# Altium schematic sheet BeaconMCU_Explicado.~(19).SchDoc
size A4
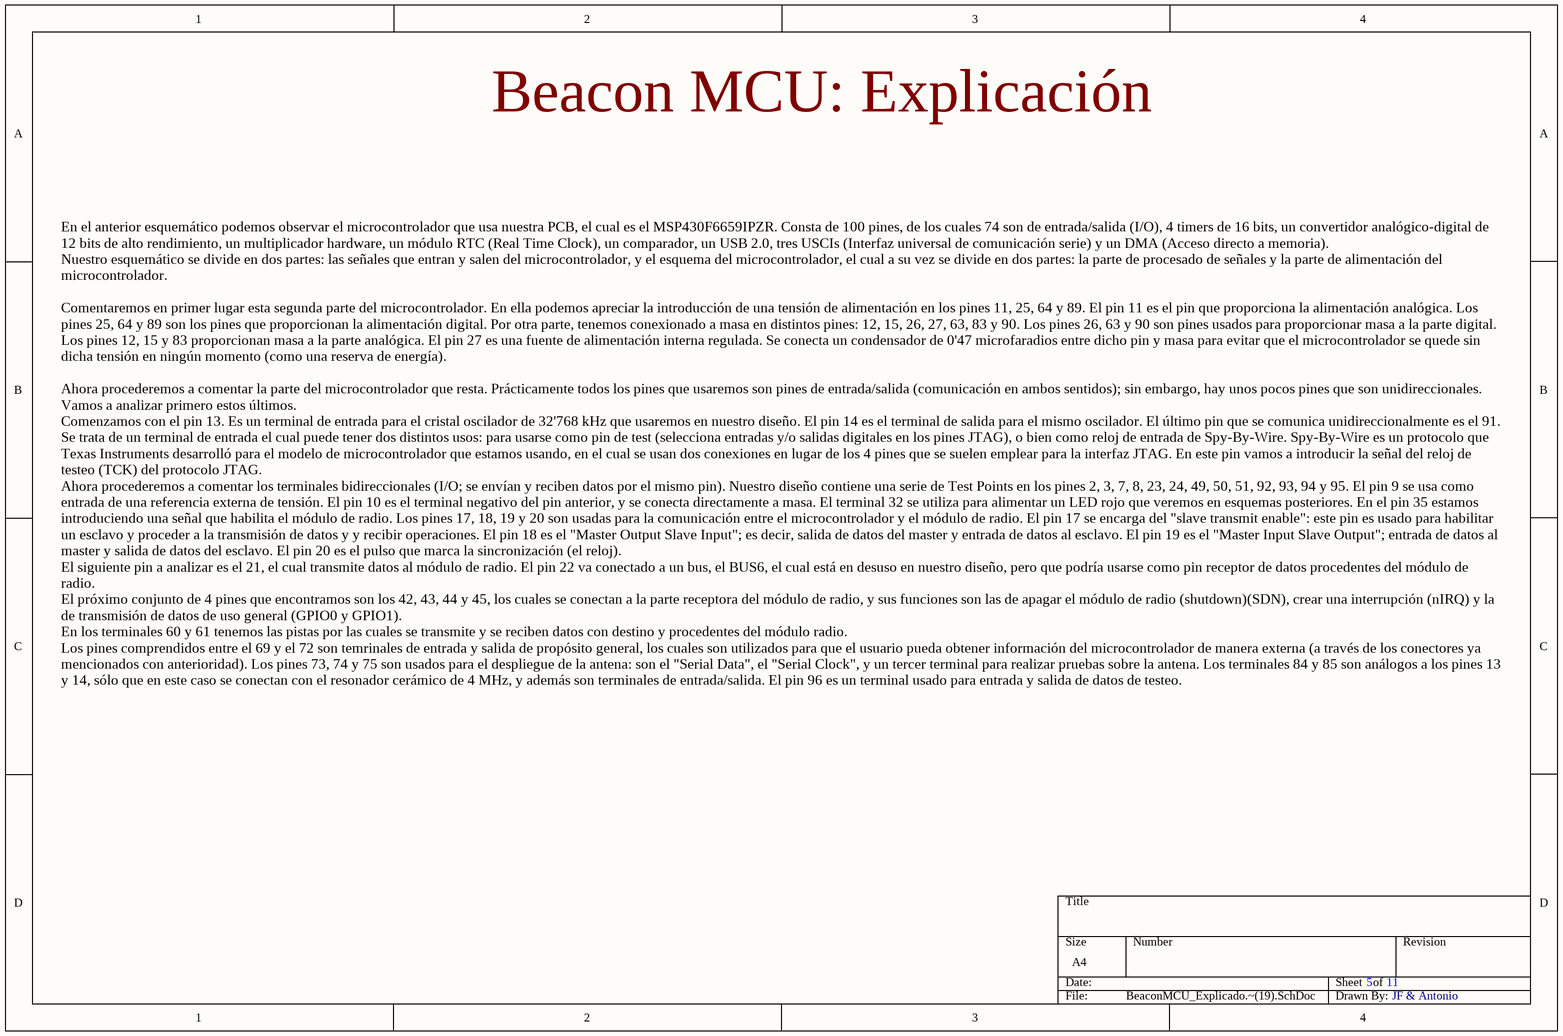
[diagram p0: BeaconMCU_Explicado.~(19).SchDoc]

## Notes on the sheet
- Beacon MCU: Explicación
- En el anterior esquemático podemos observar el microcontrolador que usa nuestra PCB, el cual es el MSP430F6659IPZR. Consta de 100 pines, de los cuales 74 son de entrada/salida (I/O), 4 timers de 16 bits, un convertidor analógico-digital de 12 bits de alto rendimiento, un multiplicador hardware, un módulo RTC (Real Time Clock), un comparador, un USB 2.0, tres USCIs (Interfaz universal de comunicación serie) y un DMA (Acceso directo a memoria).
  Nuestro esquemático se divide en dos partes: las señales que entran y salen del microcontrolador, y el esquema del microcontrolador, el cual a su vez se divide en dos partes: la parte de procesado de señales y la parte de alimentación del microcontrolador.
  Comentaremos en primer lugar esta segunda parte del microcontrolador. En ella podemos apreciar la introducción de una tensión de alimentación en los pines 11, 25, 64 y 89. El pin 11 es el pin que proporciona la alimentación analógica. Los pines 25, 64 y 89 son los pines que proporcionan la alimentación digital. Por otra parte, tenemos conexionado a masa en distintos pines: 12, 15, 26, 27, 63, 83 y 90. Los pines 26, 63 y 90 son pines usados para proporcionar masa a la parte digital. Los pines 12, 15 y 83 proporcionan masa a la parte analógica. El pin 27 es una fuente de alimentación interna regulada. Se conecta un condensador de 0'47 microfaradios entre dicho pin y masa para evitar que el microcontrolador se quede sin dicha tensión en ningún momento (como una reserva de energía).
  Ahora procederemos a comentar la parte del microcontrolador que resta. Prácticamente todos los pines que usaremos son pines de entrada/salida (comunicación en ambos sentidos); sin embargo, hay unos pocos pines que son unidireccionales. Vamos a analizar primero estos últimos.
  Comenzamos con el pin 13. Es un terminal de entrada para el cristal oscilador de 32'768 kHz que usaremos en nuestro diseño. El pin 14 es el terminal de salida para el mismo oscilador. El último pin que se comunica unidireccionalmente es el 91. Se trata de un terminal de entrada el cual puede tener dos distintos usos: para usarse como pin de test (selecciona entradas y/o salidas digitales en los pines JTAG), o bien como reloj de entrada de Spy-By-Wire. Spy-By-Wire es un protocolo que Texas Instruments desarrolló para el modelo de microcontrolador que estamos usando, en el cual se usan dos conexiones en lugar de los 4 pines que se suelen emplear para la interfaz JTAG. En este pin vamos a introducir la señal del reloj de testeo (TCK) del protocolo JTAG.
  Ahora procederemos a comentar los terminales bidireccionales (I/O; se envían y reciben datos por el mismo pin). Nuestro diseño contiene una serie de Test Points en los pines 2, 3, 7, 8, 23, 24, 49, 50, 51, 92, 93, 94 y 95. El pin 9 se usa como entrada de una referencia externa de tensión. El pin 10 es el terminal negativo del pin anterior, y se conecta directamente a masa. El terminal 32 se utiliza para alimentar un LED rojo que veremos en esquemas posteriores. En el pin 35 estamos introduciendo una señal que habilita el módulo de radio. Los pines 17, 18, 19 y 20 son usadas para la comunicación entre el microcontrolador y el módulo de radio. El pin 17 se encarga del "slave transmit enable": este pin es usado para habilitar un esclavo y proceder a la transmisión de datos y y recibir operaciones. El pin 18 es el "Master Output Slave Input"; es decir, salida de datos del master y entrada de datos al esclavo. El pin 19 es el "Master Input Slave Output"; entrada de datos al master y salida de datos del esclavo. El pin 20 es el pulso que marca la sincronización (el reloj).
  El siguiente pin a analizar es el 21, el cual transmite datos al módulo de radio. El pin 22 va conectado a un bus, el BUS6, el cual está en desuso en nuestro diseño, pero que podría usarse como pin receptor de datos procedentes del módulo de radio.
  El próximo conjunto de 4 pines que encontramos son los 42, 43, 44 y 45, los cuales se conectan a la parte receptora del módulo de radio, y sus funciones son las de apagar el módulo de radio (shutdown)(SDN), crear una interrupción (nIRQ) y la de transmisión de datos de uso general (GPIO0 y GPIO1).
  En los terminales 60 y 61 tenemos las pistas por las cuales se transmite y se reciben datos con destino y procedentes del módulo radio.
  Los pines comprendidos entre el 69 y el 72 son temrinales de entrada y salida de propósito general, los cuales son utilizados para que el usuario pueda obtener información del microcontrolador de manera externa (a través de los conectores ya mencionados con anterioridad). Los pines 73, 74 y 75 son usados para el despliegue de la antena: son el "Serial Data", el "Serial Clock", y un tercer terminal para realizar pruebas sobre la antena. Los terminales 84 y 85 son análogos a los pines 13 y 14, sólo que en este caso se conectan con el resonador cerámico de 4 MHz, y además son terminales de entrada/salida. El pin 96 es un terminal usado para entrada y salida de datos de testeo.
- 5
- 11
- JF & Antonio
